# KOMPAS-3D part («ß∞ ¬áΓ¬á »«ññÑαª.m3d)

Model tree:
1. Эскиз:9
2. Операция выдавливания:9
     Расстояние 1 = 11; Расстояние 2 = 1
3. Эскиз:10
4. Операция выдавливания:10
     Расстояние 1 = 7.3; Расстояние 2 = 1
5. Эскиз:11
6. Операция выдавливания:11
     Расстояние 1 = 1.5; Расстояние 2 = 1
7. Скругление:4
     Радиус = 0.5
8. Скругление:5
     Радиус = 0.1
9. Условное изображение резьбы:3
     Длина резьбы = 10.9; Шаг резьбы = 1.5; Номинальный диаметр резьбы = 5
10. Скругление:6
     Радиус = 0.1

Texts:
  ось катка поддерж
